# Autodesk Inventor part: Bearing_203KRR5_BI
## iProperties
Created: 2008-11
Part Number: Bearing_203KRR5_BI
Document SubType Name: Modeling
Designer: ETUDIANT
Author: ETUDIANT
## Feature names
1. Révolution1 [Revolution]
